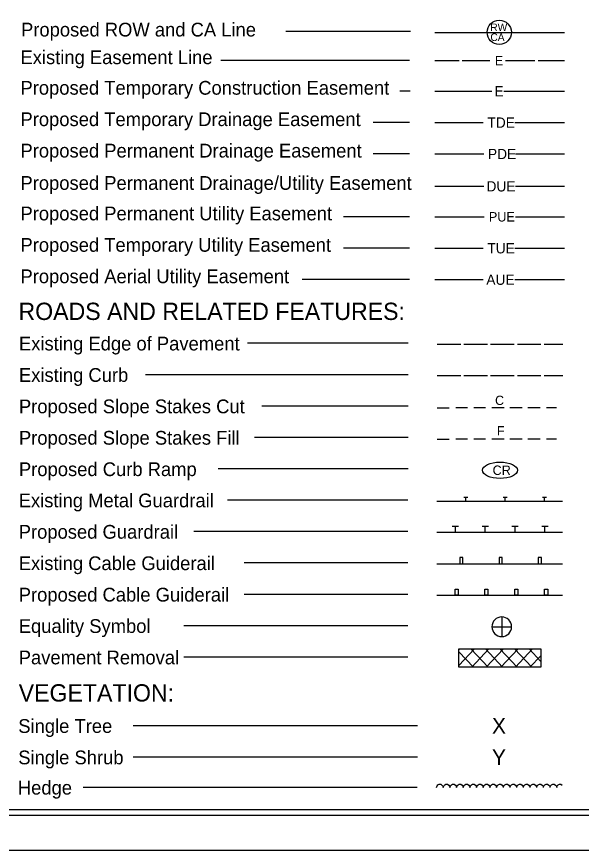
# Model space of a CAD drawing. Extents: x 2078953 to 2080637, y 324331 to 325431.
# Drawn here: x 2079515 to 2079875, y 324331 to 324862 of the extents above; entities that cross this region are included whole.
import ezdxf

# ---------------------------------------------------------------- set-up
doc = ezdxf.new("R2010")
doc.units = 0
for name, color, linetype in [('Prop Easement Permanent Drainage Utility', 7, 'Continuous'), ('Prop WCC CELL', 7, 'Continuous'), ('Sheet Cutting Line CELL', 7, 'Continuous'), ('Sheet Plot Border Inside CELL', 7, 'Continuous'), ('Sheet Plot Border Outside CELL', 7, 'Continuous'), ('Sheet Symbology CELL', 7, 'Continuous')]:
    doc.layers.add(name, color=color, linetype=linetype)

msp = doc.modelspace()

# ---------------------------------------------------------------- linework, layer by layer
at = {"layer": 'Prop Easement Permanent Drainage Utility'}
for p, q in [((2079781.58, 324753.84), (2079812.88, 324753.84)), ((2079832.88, 324753.84), (2079864.08, 324753.84))]:
    msp.add_line(p, q, dxfattribs=at)
at = {"layer": 'Prop WCC CELL'}
msp.add_ellipse((2079823.08, 324573.02), major_axis=(11.21, 0), ratio=0.462467, dxfattribs=at)
at = {"layer": 'Sheet Cutting Line CELL'}
msp.add_line((2078952.7, 324331.07), (2080636.7, 324331.07), dxfattribs=at)
at = {"layer": 'Sheet Plot Border Inside CELL'}
msp.add_lwpolyline([(2078965.7, 324353.52), (2080632.2, 324353.52), (2080632.2, 325408.62), (2078965.7, 325408.62)], close=True, dxfattribs=at)
at = {"layer": 'Sheet Plot Border Outside CELL'}
msp.add_lwpolyline([(2078952.7, 324331.07), (2080636.7, 324331.07), (2080636.7, 325431.07), (2078952.7, 325431.07)], close=True, dxfattribs=at)
at = {"layer": 'Sheet Symbology CELL'}
for p, q in [((2079766.19, 324852.49), (2079686.83, 324852.49)), ((2079781.59, 324851.72), (2079864.09, 324851.72)), ((2079765.55, 324833.87), (2079645.27, 324833.87)), ((2079781.58, 324833.87), (2079797.09, 324833.87)), ((2079799.09, 324833.87), (2079816.59, 324833.87)), ((2079826.59, 324833.87), (2079845.34, 324833.87)), ((2079847.34, 324833.87), (2079864.08, 324833.87)), ((2079765.94, 324814.42), (2079759.26, 324814.42)), ((2079781.58, 324814.42), (2079784.19, 324814.42)), ((2079784.19, 324814.42), (2079817.94, 324814.42)), ((2079825.44, 324814.42), (2079859.19, 324814.42)), ((2079859.19, 324814.42), (2079864.08, 324814.42)), ((2079765.55, 324794.42), (2079742.4, 324794.42)), ((2079781.58, 324794.42), (2079784.93, 324794.42)), ((2079784.93, 324794.42), (2079812.43, 324794.42)), ((2079832.43, 324794.42), (2079859.93, 324794.42)), ((2079859.93, 324794.42), (2079864.08, 324794.42)), ((2079765.55, 324774.42), (2079742.4, 324774.42)), ((2079781.58, 324774.42), (2079785.38, 324774.42)), ((2079785.38, 324774.42), (2079812.88, 324774.42)), ((2079832.88, 324774.42), (2079860.38, 324774.42)), ((2079860.38, 324774.42), (2079864.08, 324774.42)), ((2079765.55, 324734.41), (2079723.41, 324734.41)), ((2079781.58, 324734.41), (2079785.42, 324734.41)), ((2079785.42, 324734.41), (2079812.92, 324734.41)), ((2079832.92, 324734.41), (2079860.42, 324734.41)), ((2079860.42, 324734.41), (2079864.08, 324734.41)), ((2079765.55, 324714.41), (2079723.41, 324714.41)), ((2079781.58, 324714.41), (2079784.93, 324714.41)), ((2079784.93, 324714.41), (2079812.43, 324714.41)), ((2079832.43, 324714.41), (2079859.93, 324714.41)), ((2079859.93, 324714.41), (2079864.08, 324714.41)), ((2079765.55, 324694.41), (2079697.1, 324694.41)), ((2079781.58, 324694.41), (2079784.93, 324694.41)), ((2079784.93, 324694.41), (2079812.43, 324694.41)), ((2079832.43, 324694.41), (2079859.93, 324694.41)), ((2079859.93, 324694.41), (2079864.08, 324694.41)), ((2079764.59, 324653.88), (2079662.24, 324653.88)), ((2079783.12, 324653.31), (2079798.12, 324653.31)), ((2079800.12, 324653.31), (2079815.12, 324653.31)), ((2079817.12, 324653.31), (2079832.12, 324653.31)), ((2079834.12, 324653.31), (2079849.12, 324653.31)), ((2079851.12, 324653.31), (2079863.12, 324653.31)), ((2079764.59, 324633.88), (2079597.44, 324633.88)), ((2079783.12, 324633.31), (2079798.12, 324633.31)), ((2079800.12, 324633.31), (2079815.12, 324633.31)), ((2079817.12, 324633.31), (2079832.12, 324633.31)), ((2079834.12, 324633.31), (2079849.12, 324633.31)), ((2079851.12, 324633.31), (2079863.12, 324633.31)), ((2079764.59, 324613.88), (2079671.4, 324613.88)), ((2079783.12, 324612.83), (2079790.72, 324612.83)), ((2079802.42, 324612.83), (2079794.87, 324612.83)), ((2079813.92, 324612.83), (2079806.32, 324612.83)), ((2079825.67, 324612.83), (2079817.87, 324612.83)), ((2079837.12, 324612.83), (2079829.37, 324612.83)), ((2079848.67, 324612.83), (2079840.82, 324612.83)), ((2079858.97, 324612.83), (2079852.57, 324612.83)), ((2079764.59, 324593.88), (2079666.85, 324593.88)), ((2079783.12, 324592.83), (2079790.72, 324592.83)), ((2079802.42, 324592.83), (2079794.87, 324592.83)), ((2079813.92, 324592.83), (2079806.32, 324592.83)), ((2079825.67, 324592.83), (2079817.87, 324592.83)), ((2079837.12, 324592.83), (2079829.37, 324592.83)), ((2079848.67, 324592.83), (2079840.82, 324592.83)), ((2079858.97, 324592.83), (2079852.57, 324592.83)), ((2079764.59, 324573.88), (2079643.66, 324573.88)), ((2079800.1, 324555.93), (2079802.6, 324555.93)), ((2079801.35, 324553.43), (2079801.35, 324555.93)), ((2079825.1, 324555.93), (2079827.6, 324555.93)), ((2079826.35, 324553.43), (2079826.35, 324555.93)), ((2079850.1, 324555.93), (2079852.6, 324555.93)), ((2079851.35, 324553.43), (2079851.35, 324555.93)), ((2079764.43, 324554), (2079649.6, 324554)), ((2079782.96, 324553.43), (2079862.96, 324553.43)), ((2079792.69, 324537.38), (2079796.69, 324537.38)), ((2079794.69, 324533.43), (2079794.69, 324537.38)), ((2079811.69, 324537.38), (2079815.69, 324537.38)), ((2079813.69, 324533.43), (2079813.69, 324537.38)), ((2079830.69, 324537.38), (2079834.69, 324537.38)), ((2079832.69, 324533.43), (2079832.69, 324537.38)), ((2079849.69, 324537.38), (2079853.69, 324537.38)), ((2079851.69, 324533.43), (2079851.69, 324537.38)), ((2079764.43, 324534), (2079628.2, 324534)), ((2079862.96, 324533.43), (2079782.96, 324533.43)), ((2079764.43, 324514), (2079660.13, 324514)), ((2079782.96, 324513.43), (2079862.96, 324513.43)), ((2079764.43, 324494), (2079660.13, 324494)), ((2079782.96, 324493.43), (2079862.96, 324493.43)), ((2079824.19, 324479.67), (2079824.19, 324473.42)), ((2079764.43, 324474), (2079621.81, 324474)), ((2079817.94, 324473.42), (2079824.19, 324473.42)), ((2079824.19, 324473.42), (2079824.19, 324467.17)), ((2079824.19, 324473.42), (2079830.44, 324473.42)), ((2079796.91, 324459.29), (2079849.01, 324459.29)), ((2079796.91, 324447.59), (2079796.91, 324459.29)), ((2079796.91, 324458.69), (2079797.46, 324459.29)), ((2079796.91, 324448.74), (2079806.76, 324459.29)), ((2079806.16, 324447.59), (2079796.91, 324457.49)), ((2079815.46, 324447.59), (2079804.46, 324459.29)), ((2079805.06, 324447.59), (2079816.06, 324459.29)), ((2079824.71, 324447.59), (2079813.76, 324459.29)), ((2079814.31, 324447.59), (2079825.36, 324459.29)), ((2079834.01, 324447.59), (2079823.01, 324459.29)), ((2079823.61, 324447.59), (2079834.61, 324459.29)), ((2079843.31, 324447.59), (2079832.26, 324459.29)), ((2079832.91, 324447.59), (2079843.86, 324459.29)), ((2079849.01, 324451.34), (2079841.56, 324459.29)), ((2079842.16, 324447.59), (2079849.01, 324454.89)), ((2079849.01, 324459.29), (2079849.01, 324447.59)), ((2079764.43, 324454), (2079621.81, 324454)), ((2079849.01, 324447.59), (2079796.91, 324447.59)), ((2079770.57, 324410.36), (2079589.45, 324410.36)), ((2079770.57, 324390.36), (2079589.45, 324390.36)), ((2079770.3, 324371.1), (2079557.62, 324371.1)), ((2079782.7, 324371.1), (2079783, 324372.05)), ((2079783, 324372.05), (2079783.6, 324372.7)), ((2079783.6, 324372.7), (2079784.4, 324373.15)), ((2079784.4, 324373.15), (2079785.35, 324373.15)), ((2079785.35, 324373.15), (2079786.15, 324372.65)), ((2079786.15, 324372.65), (2079786.7, 324372)), ((2079786.7, 324372), (2079786.9, 324371.15)), ((2079786.95, 324371.1), (2079787.25, 324372.05)), ((2079787.25, 324372.05), (2079787.85, 324372.7)), ((2079787.85, 324372.7), (2079788.65, 324373.15)), ((2079788.65, 324373.15), (2079789.6, 324373.15)), ((2079789.6, 324373.15), (2079790.4, 324372.65)), ((2079790.4, 324372.65), (2079790.95, 324372)), ((2079790.95, 324372), (2079791.15, 324371.15)), ((2079791.2, 324371.1), (2079791.5, 324372.05)), ((2079791.5, 324372.05), (2079792.1, 324372.7)), ((2079792.1, 324372.7), (2079792.9, 324373.15)), ((2079792.9, 324373.15), (2079793.85, 324373.15)), ((2079793.85, 324373.15), (2079794.65, 324372.65)), ((2079794.65, 324372.65), (2079795.2, 324372)), ((2079795.2, 324372), (2079795.4, 324371.15)), ((2079795.45, 324371.1), (2079795.75, 324372.05)), ((2079795.75, 324372.05), (2079796.35, 324372.7)), ((2079796.35, 324372.7), (2079797.15, 324373.15)), ((2079797.15, 324373.15), (2079798.1, 324373.15)), ((2079798.1, 324373.15), (2079798.9, 324372.65)), ((2079798.9, 324372.65), (2079799.45, 324372)), ((2079799.45, 324372), (2079799.65, 324371.15)), ((2079799.7, 324371.1), (2079800, 324372.05)), ((2079800, 324372.05), (2079800.6, 324372.7)), ((2079800.6, 324372.7), (2079801.4, 324373.15)), ((2079801.4, 324373.15), (2079802.35, 324373.15)), ((2079802.35, 324373.15), (2079803.15, 324372.65)), ((2079803.15, 324372.65), (2079803.7, 324372)), ((2079803.7, 324372), (2079803.9, 324371.15)), ((2079803.95, 324371.1), (2079804.25, 324372.05)), ((2079804.25, 324372.05), (2079804.85, 324372.7)), ((2079804.85, 324372.7), (2079805.65, 324373.15)), ((2079805.65, 324373.15), (2079806.6, 324373.15)), ((2079806.6, 324373.15), (2079807.4, 324372.65)), ((2079807.4, 324372.65), (2079807.95, 324372)), ((2079807.95, 324372), (2079808.15, 324371.15)), ((2079808.2, 324371.1), (2079808.5, 324372.05)), ((2079808.5, 324372.05), (2079809.1, 324372.7)), ((2079809.1, 324372.7), (2079809.9, 324373.15)), ((2079809.9, 324373.15), (2079810.85, 324373.15)), ((2079810.85, 324373.15), (2079811.65, 324372.65)), ((2079811.65, 324372.65), (2079812.2, 324372)), ((2079812.2, 324372), (2079812.4, 324371.15)), ((2079812.45, 324371.1), (2079812.75, 324372.05)), ((2079812.75, 324372.05), (2079813.35, 324372.7)), ((2079813.35, 324372.7), (2079814.15, 324373.15)), ((2079814.15, 324373.15), (2079815.1, 324373.15)), ((2079815.1, 324373.15), (2079815.9, 324372.65)), ((2079815.9, 324372.65), (2079816.45, 324372)), ((2079816.45, 324372), (2079816.65, 324371.15)), ((2079816.7, 324371.1), (2079817, 324372.05)), ((2079817, 324372.05), (2079817.6, 324372.7)), ((2079817.6, 324372.7), (2079818.4, 324373.15)), ((2079818.4, 324373.15), (2079819.35, 324373.15)), ((2079819.35, 324373.15), (2079820.15, 324372.65)), ((2079820.15, 324372.65), (2079820.7, 324372)), ((2079820.7, 324372), (2079820.9, 324371.15)), ((2079820.95, 324371.1), (2079821.25, 324372.05)), ((2079821.25, 324372.05), (2079821.85, 324372.7)), ((2079821.85, 324372.7), (2079822.65, 324373.15)), ((2079822.65, 324373.15), (2079823.6, 324373.15)), ((2079823.6, 324373.15), (2079824.4, 324372.65)), ((2079824.4, 324372.65), (2079824.95, 324372)), ((2079824.95, 324372), (2079825.15, 324371.15)), ((2079825.2, 324371.1), (2079825.5, 324372.05)), ((2079825.5, 324372.05), (2079826.1, 324372.7)), ((2079826.1, 324372.7), (2079826.9, 324373.15)), ((2079826.9, 324373.15), (2079827.85, 324373.15)), ((2079827.85, 324373.15), (2079828.65, 324372.65)), ((2079828.65, 324372.65), (2079829.2, 324372)), ((2079829.2, 324372), (2079829.4, 324371.15)), ((2079829.45, 324371.1), (2079829.75, 324372.05)), ((2079829.75, 324372.05), (2079830.35, 324372.7)), ((2079830.35, 324372.7), (2079831.15, 324373.15)), ((2079831.15, 324373.15), (2079832.1, 324373.15)), ((2079832.1, 324373.15), (2079832.9, 324372.65)), ((2079832.9, 324372.65), (2079833.45, 324372)), ((2079833.45, 324372), (2079833.65, 324371.15)), ((2079833.7, 324371.1), (2079834, 324372.05)), ((2079834, 324372.05), (2079834.6, 324372.7)), ((2079834.6, 324372.7), (2079835.4, 324373.15)), ((2079835.4, 324373.15), (2079836.35, 324373.15)), ((2079836.35, 324373.15), (2079837.15, 324372.65)), ((2079837.15, 324372.65), (2079837.7, 324372)), ((2079837.7, 324372), (2079837.9, 324371.15)), ((2079837.95, 324371.1), (2079838.25, 324372.05)), ((2079838.25, 324372.05), (2079838.85, 324372.7)), ((2079838.85, 324372.7), (2079839.65, 324373.15)), ((2079839.65, 324373.15), (2079840.6, 324373.15)), ((2079840.6, 324373.15), (2079841.4, 324372.65)), ((2079841.4, 324372.65), (2079841.95, 324372)), ((2079841.95, 324372), (2079842.15, 324371.15)), ((2079842.2, 324371.1), (2079842.5, 324372.05)), ((2079842.5, 324372.05), (2079843.1, 324372.7)), ((2079843.1, 324372.7), (2079843.9, 324373.15)), ((2079843.9, 324373.15), (2079844.85, 324373.15)), ((2079844.85, 324373.15), (2079845.65, 324372.65)), ((2079845.65, 324372.65), (2079846.2, 324372)), ((2079846.2, 324372), (2079846.4, 324371.15)), ((2079846.45, 324371.1), (2079846.75, 324372.05)), ((2079846.75, 324372.05), (2079847.35, 324372.7)), ((2079847.35, 324372.7), (2079848.15, 324373.15)), ((2079848.15, 324373.15), (2079849.1, 324373.15)), ((2079849.1, 324373.15), (2079849.9, 324372.65)), ((2079849.9, 324372.65), (2079850.45, 324372)), ((2079850.45, 324372), (2079850.65, 324371.15)), ((2079850.7, 324371.1), (2079851, 324372.05)), ((2079851, 324372.05), (2079851.6, 324372.7)), ((2079851.6, 324372.7), (2079852.4, 324373.15)), ((2079852.4, 324373.15), (2079853.35, 324373.15)), ((2079853.35, 324373.15), (2079854.15, 324372.65)), ((2079854.15, 324372.65), (2079854.7, 324372)), ((2079854.7, 324372), (2079854.9, 324371.15)), ((2079854.95, 324371.1), (2079855.25, 324372.05)), ((2079855.25, 324372.05), (2079855.85, 324372.7)), ((2079855.85, 324372.7), (2079856.65, 324373.15)), ((2079856.65, 324373.15), (2079857.6, 324373.15)), ((2079857.6, 324373.15), (2079858.4, 324372.65)), ((2079858.4, 324372.65), (2079858.95, 324372)), ((2079858.95, 324372), (2079859.15, 324371.15)), ((2079859.2, 324371.1), (2079859.5, 324372.05)), ((2079859.5, 324372.05), (2079860.1, 324372.7)), ((2079860.1, 324372.7), (2079860.9, 324373.15)), ((2079860.9, 324373.15), (2079861.85, 324373.15)), ((2079861.85, 324373.15), (2079862.65, 324372.65)), ((2079862.65, 324372.65), (2079862.7, 324372.6))]:
    msp.add_line(p, q, dxfattribs=at)
for points in [[(2080619.7, 325406.07), (2079119.7, 325406.07), (2079119.7, 324357.08), (2080619.7, 324357.08)], [(2079797.44, 324513.43), (2079799.44, 324513.43), (2079799.44, 324517.43), (2079797.44, 324517.43)], [(2079822.44, 324513.43), (2079824.44, 324513.43), (2079824.44, 324517.43), (2079822.44, 324517.43)], [(2079847.44, 324513.43), (2079849.44, 324513.43), (2079849.44, 324517.43), (2079847.44, 324517.43)], [(2079794.43, 324497.43), (2079796.43, 324497.43), (2079796.43, 324493.43), (2079794.43, 324493.43)], [(2079813.43, 324497.43), (2079815.43, 324497.43), (2079815.43, 324493.43), (2079813.43, 324493.43)], [(2079832.43, 324497.43), (2079834.43, 324497.43), (2079834.43, 324493.43), (2079832.43, 324493.43)], [(2079851.43, 324497.43), (2079853.43, 324497.43), (2079853.43, 324493.43), (2079851.43, 324493.43)]]:
    msp.add_lwpolyline(points, close=True, dxfattribs=at)
msp.add_circle((2079822.58, 324851.87), 7.72, dxfattribs=at)
for start, end in [(89.9944, 179.9989), (359.9944, 89.9989), (179.9944, 269.9989), (269.9944, 359.9989)]:
    msp.add_arc((2079824.19, 324473.41), 6.25, start, end, dxfattribs=at)

# ---------------------------------------------------------------- texts
at = {"layer": 'Prop Easement Permanent Drainage Utility'}
msp.add_text('DUE', height=6.55, dxfattribs=at).set_placement((2079814.47, 324750.54))
at = {"layer": 'Prop WCC CELL'}
msp.add_text('CR', height=6, dxfattribs=at).set_placement((2079818.37, 324570.06))
at = {"layer": 'Sheet Symbology CELL'}
for s, height, p in [('Proposed ROW and CA Line', 8.75, (2079518.16, 324849.21)), ('RW', 4.838, (2079816.91, 324852.64)), ('CA', 4.838, (2079816.97, 324846.35)), ('Existing Easement Line', 8.75, (2079517.8, 324831.61)), ('E', 6, (2079819.79, 324830.87)), ('Proposed Temporary Construction Easement', 8.75, (2079517.8, 324812.16)), ('E', 6.55, (2079819.54, 324811.12)), ('Proposed Temporary Drainage Easement', 8.75, (2079517.8, 324792.16)), ('TDE', 6.55, (2079815.03, 324791.12)), ('Proposed Permanent Drainage Easement', 8.75, (2079517.8, 324772.16)), ('PDE', 6.55, (2079815.38, 324771.12)), ('Proposed Permanent Drainage/Utility Easement', 8.75, (2079517.8, 324751.58)), ('Proposed Permanent Utility Easement', 8.75, (2079517.8, 324732.15)), ('PUE', 6, (2079816.02, 324731.41)), ('Proposed Temporary Utility Easement', 8.75, (2079517.8, 324712.15)), ('TUE', 6.55, (2079815.01, 324711.11)), ('Proposed Aerial Utility Easement', 8.75, (2079517.8, 324692.15)), ('AUE', 6.55, (2079814.36, 324691.11)), ('ROADS AND RELATED FEATURES:', 11, (2079516.54, 324668.73)), ('Existing Edge of Pavement', 8.75, (2079516.84, 324649.33)), ('Existing Curb', 8.75, (2079516.84, 324629.33)), ('C', 5.93, (2079819.92, 324614.57)), ('Proposed Slope Stakes Cut', 8.75, (2079516.84, 324609.33)), ('Proposed Slope Stakes Fill', 8.75, (2079516.84, 324589.33)), ('F', 5.93, (2079821.12, 324595.2)), ('Proposed Curb Ramp', 8.75, (2079516.84, 324569.33)), ('Existing Metal Guardrail', 8.75, (2079516.68, 324549.45)), ('Proposed Guardrail', 8.75, (2079516.7, 324529.47)), ('Existing Cable Guiderail', 8.75, (2079516.7, 324509.47)), ('Proposed Cable Guiderail', 8.75, (2079516.7, 324489.47)), ('Equality Symbol', 8.75, (2079516.7, 324469.47)), ('Pavement Removal', 8.75, (2079516.7, 324449.47)), ('VEGETATION:', 11, (2079516.68, 324425.81)), ('Single Tree', 8.75, (2079516.41, 324405.83)), ('X', 10, (2079817.96, 324405.36)), ('Single Shrub', 8.75, (2079516.41, 324385.83)), ('Y', 10, (2079817.96, 324385.36)), ('Hedge', 8.75, (2079516.14, 324366.58))]:
    msp.add_text(s, height=height, dxfattribs=at).set_placement(p)

doc.saveas('drawing.dxf')
